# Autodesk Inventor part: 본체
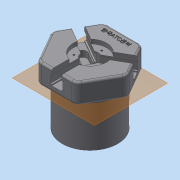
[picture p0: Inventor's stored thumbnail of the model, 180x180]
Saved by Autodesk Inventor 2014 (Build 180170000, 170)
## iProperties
Created: 2023-03
Part Number: 본체
Material: 강철
Document SubType Name: Modeling
Designer: mdu-01
Density: 1 g/cm^3
Appearance: 기본값
Author: mdu-01
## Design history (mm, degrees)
sketch "스케치1"
  geometry: C1 r 40 at (0, 0); 1 further point
  constraints: 1 centre point, 1 coincident
  dimensions: "d0" = 80 diameter of C1
extrude "돌출1" new body sketch "스케치1" distance "d1" = 65; taper "d2" = 0 deg
sketch "스케치2"
  geometry: L1 (30.6, 43)-(52.539, 5); L2 (52.539, -5)-(30.6, -43); L3 (21.939, -48)-(-21.939, -48); L4 (-30.6, -43)-(-52.539, -5); L5 (-52.539, 5)-(-30.6, 43); L6 (-21.939, 48)-(21.939, 48); A1 r 10 centre (-43.879, 0) between (-52.539, 5) and (-52.539, -5); A2 r 10 centre (-21.939, -38) between (-30.6, -43) and (-21.939, -48); A3 r 10 centre (21.939, -38) between (21.939, -48) and (30.6, -43); A4 r 10 centre (43.879, 0) between (52.539, -5) and (52.539, 5); A5 r 10 centre (21.939, 38) between (30.6, 43) and (21.939, 48); A6 r 10 centre (-21.939, 38) between (-21.939, 48) and (-30.6, 43); 8 further points
  constraints: 12 end point, 12 point on circle, 12 point on line, 12 tangent, 6 centre point, 5 equal radius, 1 coincident, 1 horizontal alignment, 13 other
  dimensions: "d3" = 96 distance between parallel lines of L3 L6; "d4" = 10 radius of A1
extrude "돌출2" join sketch "스케치2" distance "d5" = 29; taper "d6" = 0 deg
fillet "모깎기1" dims "d7" = 3
sketch "스케치3"
  geometry: L1 (0, 0)-(0, 94); L2 (0, 0)-(25, 0); L3 (25, 0)-(25, 54); L4 (25, 54)-(9, 54); L5 (8, 55)-(8, 57.4); L6 (8, 57.4)-(9.6, 57.4); L7 (10, 57.8)-(10, 60.2); L8 (9.6, 60.6)-(8, 60.6); L9 (8, 60.6)-(8, 63); L10 (9, 64)-(12, 64); L11 (12, 64)-(12, 88); L12 (12, 88)-(24, 88); L13 (24, 88)-(24, 94); L14 (24, 94)-(0, 94); L15 (-21.939, 94)-(21.939, 94) reference; L16 (8, 63)-(9, 64); L17 (8, 55)-(9, 54); A1 r 0.4 centre (9.6, 60.2) between (10, 60.2) and (9.6, 60.6); A2 r 0.4 centre (9.6, 57.8) between (9.6, 57.4) and (10, 57.8); 3 further points
  constraints: 32 end point, 6 parallel, 6 perpendicular, 6 point on line, 4 point on circle, 4 tangent, 2 centre point, 1 collinear, 1 equal radius, 1 midpoint, 1 vertical
  dimensions: "d8" = 50 diameter of L3 L1; "d10" = 48 diameter of L13 L1; "d11" = 6 distance between parallel lines of L12 L14; "d12" = 24 diameter of L11 L1; "d13" = 16 diameter of L9 L1; "d14" = 30 distance between parallel lines of L10 L14; "d15" = 54 distance between parallel lines of L4 L2; "d16" = 5 distance from line of point (10, 59) L4; "d17" = 20 diameter of L7 L1; "d18" = 0.4 radius of A1; "d19" = 3.2 distance between parallel lines of L6 L8; "d20" = 1 distance of L9.end point (8, 64); "d21" = 1 distance of L10.start point (8, 64) (= d20); "d22" = 1 distance of L5.start point (8, 54) (= d20); "d23" = 1 distance of L4.end point (8, 54) (= d22)
revolve "회전1" sketch "스케치3" stored, may be unused: angle "d24" = 90 deg
chamfer "모따기1" distance "d25" = 1; stored, may be unused: second distance "d26" = 2, angle "d27" = 45 deg
sketch "스케치4"
  geometry: L1 (21.939, -91)-(21.939, 3); L2 (29.139, -18)-(29.139, -16.482); L3 (30.939, -16)-(30.939, -5); L4 (29.139, -4.518)-(29.139, 3); L5 (14.739, -18)-(14.739, -16.482); L6 (12.939, -16)-(12.939, -5); L7 (14.739, -4.518)-(14.739, 3); L8 (14.739, 3)-(29.139, 3); L9 (14.739, -18)-(29.139, -18); L10 (43.879, 3)-(0, 3) reference; L11 (12.939, -10.5)-(30.939, -10.5); L12 (29.139, -16.482)-(30.939, -16); L13 (29.139, -4.518)-(30.939, -5); L14 (14.739, -4.518)-(12.939, -5); L15 (14.739, -16.482)-(12.939, -16)
  constraints: 28 end point, 7 symmetric about line, 3 collinear, 3 midpoint, 3 parallel, 1 perpendicular, 1 vertical
  dimensions: "d28" = 14.4 distance between parallel lines of L4 L7; "d30" = 21 distance between parallel lines of L9 L8; "d31" = 11 distance of L3.start L3.end; "d33" = 18 distance between parallel lines of L3 L6; "d34" = 30 deg angle of L12 L13; "d35" = 8 distance from line of L3.end L8
extrude "돌출3" cut sketch "스케치4" stored distance "d36" = 29; taper "d37" = 0 deg
sketch "스케치5" dims "d38" = 34
  geometry: 3 further points
  constraints: 2 vertical alignment, 1 coincident, 2 other
hole "구멍1" sketch "스케치5" at (0, 17) diameter "d39" = 2.459; stored, may be unused: countersink angle "d43" = 90 deg, drill point angle "d45" = 118 deg; dims "d40" = 6, "d41" = 4, "d42" = 2, "d44" = 8
sketch "스케치6"
  geometry: L1 (1.2, 19)-(1.2, 48); L2 (1.2, 48)-(13.2, 48); L3 (13.2, 48)-(13.2, 19); A1 r 6 centre (7.2, 19) between (1.2, 19) and (13.2, 19); 1 further point
  constraints: 6 end point, 2 point on circle, 2 tangent, 2 vertical, 1 centre point, 1 midpoint, 1 perpendicular, 1 vertical alignment
  dimensions: "d46" = 12 diameter of A1; "d48" = 29 distance from line of A1.centre L2
extrude "돌출4" cut sketch "스케치6" stored distance "d49" = 29; taper "d50" = 0 deg
sketch "스케치7"
  geometry: L1 (-12.49, -38)-(12.49, -38); A1 r 40 centre (0, 0) between (-12.49, -38) and (12.49, -38) reference; 1 further point
  constraints: 2 end point, 2 point on circle, 1 horizontal
  dimensions: "d54" = 38 distance from line of L1 A1.centre
extrude "돌출5" cut sketch "스케치7" distance "d55" = 57; taper "d56" = 0 deg
sketch "스케치8"
  geometry: L1 (24.98, 0)-(0, 0) reference; C1 r 2 at (12.49, 16); C2 r 2 at (12.49, 49); 2 further points
  constraints: 2 centre point, 2 vertical alignment, 1 midpoint
  dimensions: "d57" = 4 diameter of C1; "d58" = 4 diameter of C2; "d59" = 16 distance from line of C1.centre L1; "d60" = 33 distance of C1.centre C2.centre
extrude "돌출6" cut sketch "스케치8" stored distance "d61" = 29; taper "d62" = 0 deg
hole "구멍2" sketch "스케치8" diameter "d63" = 8; stored, may be unused: countersink angle "d67" = 90 deg, drill point angle "d69" = 118 deg; dims "d64" = 9, "d65" = 4, "d66" = 2, "d68" = 11, "d81" = 0.62479, "d82" = 7.985
sketch "스케치9" dims "d70" = 64
  geometry: 3 further points
  constraints: 2 vertical alignment, 1 coincident, 2 other
hole "구멍3" sketch "스케치9" at (0, -32) diameter "d71" = 3.242; stored, may be unused: countersink angle "d75" = 90 deg, drill point angle "d77" = 118 deg; dims "d72" = 6, "d73" = 4, "d74" = 2, "d76" = 8
sketch "스케치10"
  geometry: L1 (21.939, 48)-(-21.939, 48) reference; 2 further points
  constraints: 1 vertical alignment, 1 other
  dimensions: "d83" = 10 distance from line of point (0, 38) L1
feature "엠보싱1" sketch "스케치10" dims "d3" = 96, "d4" = 10, "d84" = 0.5, "d85" = 0
node "작업 평면1"
node "작업 평면2"
node "작업 평면3"
node "작업 평면4"
node "솔리드1"
pattern_circular "원형 패턴1" dims "d52" = 360 deg
pattern_circular "원형 패턴2" dims angle "d79" = 360 deg
